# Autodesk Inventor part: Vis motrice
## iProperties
Created: 2002-05
Part Number: Vis motrice
Material: Par défaut
Document SubType Name: Modélisation
Designer: Flavien MARTY
Control State: 0
Master: False
Checked Out: False
Shininess: 20.0
Length Units: 11269
Angle Units: 11279
Time Units: 11290
Mass Units: 11283
Length Display Precision: 3
Angle Display Precision: 2
Compacted: True
Density: 0.0
Volumn: 0.0
Area: 0.0
PropertySet Name: Model Information
Author: Flavien MARTY
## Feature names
1. Extrusion1
